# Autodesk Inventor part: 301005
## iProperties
Created: 2007-11
Part Number: 301005
Document SubType Name: Modeling
Designer: TH
Density: 7.85 g/cm^3
Mass: 285.829 g
Surface Area: 737.341 cm^2
Volume: 36.4113 cm^3
Material: Steel
Description: TOP PLATE MOUNT
Component Category: Back Component
Author: TH
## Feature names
1. Extrusion1
2. Extrusion2
3. Mirror1
4. Revolution1
5. Fillet1
6. Fillet2
7. Fillet3
8. Fillet4
9. Shell1
10. Extrusion3
11. Extrusion4
12. Fillet5
13. Extrusion5
14. Fillet6
15. Fillet7
16. Extrusion6
17. Extrusion7
18. Extrusion8
19. Fillet8
20. Fillet9
21. Hole1
